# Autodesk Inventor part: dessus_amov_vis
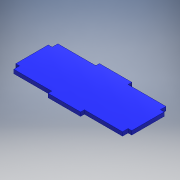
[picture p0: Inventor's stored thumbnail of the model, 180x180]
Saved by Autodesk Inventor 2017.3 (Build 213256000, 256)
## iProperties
Part Number: dessus_amov_vis
Material: Générique
Document SubType Name: Modeling
Designer: ficho
Density: 1 g/cm^3
Appearance: Bleu - Peinture murale - Brillant
Author: ficho
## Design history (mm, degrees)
sketch "Esquisse1"
  geometry: L1 (29.5, 3)-(54.8, 3); L2 (54.8, 3)-(54.8, 0); L3 (29.5, 0.15)-(29.5, 3); L4 (29.5, -37)-(54.8, -37); L5 (54.8, -37)-(54.8, -34); L6 (29.5, -34.15)-(29.5, -37); L7 (-3, -29.65)-(0, -29.65); L8 (0, -4.35)-(-3, -4.35); L9 (-3, -4.35)-(-3, -29.65); L10 (87.3, -29.65)-(84.45, -29.65); L11 (84.3, -4.35)-(87.3, -4.35); L12 (87.3, -4.35)-(87.3, -29.65); L13 (84.3, -4.65)-(87.3, -4.65) reference; L14 (84.3, -29.35)-(87.3, -29.35) reference; L15 (54.5, -37)-(54.5, -34) reference; L16 (29.8, -37)-(29.8, -34) reference; L17 (29.8, 0)-(29.8, 3) reference; L18 (54.5, 0)-(54.5, 3) reference; L19 (-3, -4.65)-(0, -4.65) reference; L20 (-3, -29.35)-(0, -29.35) reference; L21 (84.45, -34)-(54.8, -34); L22 (29.5, -34.15)-(0, -34.15); L23 (84.3, 0)-(84.3, -4.35); L24 (84.45, -29.65)-(84.45, -34); L25 (0, -34.15)-(0, -29.65); L26 (0, -4.35)-(0, 0.15); L27 (0, 0.15)-(29.5, 0.15); L28 (54.8, 0)-(84.3, 0); 2 further points
  constraints: 70 end point, 4 horizontal, 4 vertical, 2 point on line
  dimensions: "d0" = 3 distance of L5.end L4.end; "d1" = 3 distance of L11.start L11.end; "d2" = 0.3 distance between parallel lines of L14 L10 (= d3); "d3" = 0.3 distance between parallel lines of L13 L11; "d4" = 0.3 distance between parallel lines of L15 L5 (= d2); "d5" = 0.3 distance between parallel lines of L18 L2 (derived); "d6" = 0.3 distance between parallel lines of L3 L17 (= d5); "d7" = 0.3 distance between parallel lines of L6 L16 (= d4); "d8" = 0.3 distance between parallel lines of L7 L20 (= d7); "d9" = 0.3 distance between parallel lines of L8 L19 (derived)
node "Plan de construction1"
extrude "Extrusion1" new body sketch "Esquisse1" stored distance "d10" = 10; taper "d11" = 0 deg
node "Solide1"
